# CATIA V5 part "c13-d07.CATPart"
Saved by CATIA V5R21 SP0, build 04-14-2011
Part number: Part1
Bounding box of the stored display mesh (mm): x -49.812 to 35, y -44.222 to 44.222, z 0 to 30
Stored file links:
  D:\CATIA V5R21 E-RESOURCES\CATIA-V5R21\catia-v5r21-Prts\c13_catia_v5r21_prt\c13_catia_v5r21_figr_13-27\c13-d07.CATPart
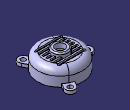
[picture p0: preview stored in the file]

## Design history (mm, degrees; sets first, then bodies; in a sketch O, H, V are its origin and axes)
Body1 (main body)
  Sketch1 on yz-plane, origin (0, 0, 0), H (0, 1, 0), V (0, 0, 1)
    line L1 (0, 0) -> (35, 0)
    line L2 (35, 0) -> (35, 15)
    arc A1 centre (25, 15) radius 10 from (35, 15) to (25, 25) ccw
    line L3 (25, 25) -> (0, 25)
    point P5 (0, 25)
    line L4 (0, 25) -> (0, 0)
    axis line L5 (0, 70.1891) -> (0, -36.6898)
    point P6 (0, 70.1891)
    "Radius" L2 L5 = 35
    distance L1 L3 = 25
    radius A1 = 10
    horizontal: L1 H
    vertical: L2 V, L4 V, L5 V
    tangency: A1 L2, L3 A1
    coincidence: P5 V, P6 V
  Shaft1: profile Sketch1, axis Sketch1.L5, angle 360
  Shell1: ExtOffset 0, Face face of Shaft1, IntOffset 2.5
  Sketch2 on face of Shaft1, origin (0, 0, 0), H (1, 0, 0), V (0, -1, 0)
    projected circle E1 centre (0, 0) radius 35 from edge [face of Shaft1 | face of Shaft1]
    projected arc E2 centre (0, 0) radius 35 from (-34.187, 7.5) to (-34.187, -7.5) ccw from edge [face of Shaft1 | face of Shaft1]
    point P1 (-34.187, 7.5)
    line L1 (-34.187, 7.5) -> (-42.5, 7.5)
    arc A1 centre (-42.5, 0) radius 7.5 from (-42.5, 7.5) to (-42.5, -7.5) ccw
    point P3 (-42.5, 0)
    line L2 (-42.5, -7.5) -> (-34.187, -7.5)
    point P5 (-34.187, -7.5)
    circle A2 centre (-42.5, 0) radius 3.75
    distance P3 V = 42.5
    radius A1 = 7.5
    radius A2 = 3.75
    coincidence: P1 E1, P5 E1, P3 H
    horizontal: L1 H, L2 H
    tangency: A1 L1, L2 A1
  Pad1: profile Sketch2, direction (0, 0, 1), length 5
  CircPattern1: of Pad1, instances 3, angular step 120 {= 360.0*1 deg/CircPattern1.AngularNumber}, axis from face of Shaft1
  Sketch3 on face of Shaft1, origin (0, 0, 25), H (1, 0, 0), V (0, 1, 0)
    construction line L1 (-20, -18) -> (20, -18)
    point P2 (20, -18)
    line L2 (-20, -16.25) -> (20, -16.25)
    line L3 (20, -19.75) -> (-20, -19.75)
    arc A1 centre (20, -18) radius 1.75 from (20, -16.25) to (20, -19.75) cw
    arc A2 centre (-20, -18) radius 1.75 from (-20, -19.75) to (-20, -16.25) cw
    length L1 = 40
    distance H L1 = 18
    distance P2 V = 20
    distance L3 L2 = 3.5
    horizontal: L1 H
    tangency: A1 L2, A2 L2, A1 L3, A2 L3
    parallelism: L1 L2
  Pocket1: profile Sketch3, direction (0, 0, -1), through (limit type 3)
  RectPattern1: of Pocket1, direction 1 instances 7, spacing 6, along yz-plane
  Sketch4 on yz-plane, origin (0, 0, 0), H (0, 1, 0), V (0, 0, 1)
    axis line L1 (0, 0) -> (0, 35.5018)
    point P2 (0, 22.5)
    line L2 (0, 22.5) -> (12.5, 22.5)
    line L3 (12.5, 22.5) -> (12.5, 28)
    arc A1 centre (10.5, 28) radius 2 from (12.5, 28) to (10.5, 30) ccw
    line L4 (10.5, 30) -> (0, 30)
    point P7 (0, 30)
    line L5 (0, 30) -> (0, 22.5)
    reference intersected line E1 (25, 22.5) -> (-25, 22.5) from face of Shell1
    "Radius" L3 L1 = 12.5
    distance L4 L2 = 7.5
    radius A1 = 2
    vertical: L1 V, L3 V, L5 V
    coincidence: P2 L1, P7 L1, L2 E1
    horizontal: L2 H, L4 H
    tangency: A1 L3, L4 A1
  Shaft2: profile Sketch4, axis Sketch4.L1, angle 360
  Sketch5 on face of Shaft2, origin (0, 0, 30), H (1, 0, 0), V (0, 1, 0)
    point P1 (0, 0)
    reference projected circle E1 centre (0, 0) radius 12.5 from edge [face of Shaft2 | face of Shaft2]
    concentricity: P1 E1
  Hole1: placed by Sketch5, at (0, 0, 30) direction (0, 0, -1), diameter 15, through (limit type 3)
